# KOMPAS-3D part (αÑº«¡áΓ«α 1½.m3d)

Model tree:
1. Эскиз:1
2. Операция выдавливания:1
     Толщина стенки 1 = 2; Толщина стенки 2 = 8; Расстояние 1 = 1
3. Эскиз:3
4. Операция выдавливания:2
     Толщина стенки 1 = 2; Толщина стенки 2 = 6; Расстояние 1 = 5
5. Эскиз:4
6. Операция выдавливания:3
     Толщина стенки 1 = 2; Толщина стенки 2 = 6; Расстояние 1 = 1
7. Эскиз:5
8. Эскиз:6
9. Операция выдавливания:4
     Толщина стенки 1 = 2; Толщина стенки 2 = 2.5; Расстояние 1 = 50
10. Эскиз:7
11. Вырезать элемент выдавливания:1
     Толщина стенки 2 = 1.5; Расстояние 1 = 40
12. Эскиз:8
13. Операция выдавливания:5
     Толщина стенки 1 = 2; Толщина стенки 2 = 2.5; Расстояние 1 = 50
14. Эскиз:9
15. Вырезать элемент выдавливания:2
     Толщина стенки 2 = 1.5; Расстояние 1 = 40
16. Эскиз:10
17. Операция выдавливания:6
     Толщина стенки 1 = 2; Толщина стенки 2 = 2.5; Расстояние 1 = 10
18. Эскиз:11
19. Операция выдавливания:7
     Толщина стенки 1 = 2; Толщина стенки 2 = 6; Расстояние 1 = 1
20. Эскиз:12
21. Операция выдавливания:8
     Толщина стенки 1 = 2; Толщина стенки 2 = 6; Расстояние 1 = 5
22. Эскиз:13
23. Операция выдавливания:9
     Толщина стенки 1 = 2; Толщина стенки 2 = 8; Расстояние 1 = 1
24. Эскиз:14
25. Вырезать элемент выдавливания:3
     Толщина стенки 2 = 1.5; Расстояние 1 = 23
26. Эскиз:15
27. Вырезать элемент выдавливания:4
     Толщина стенки 2 = 1.5; Расстояние 1 = 1
28. Эскиз:16
29. Вырезать элемент выдавливания:5
     Расстояние 1 = 150
30. Эскиз:17
31. Операция выдавливания:10
     Толщина стенки 1 = 8; Расстояние 1 = 10; Расстояние 2 = 0.4
